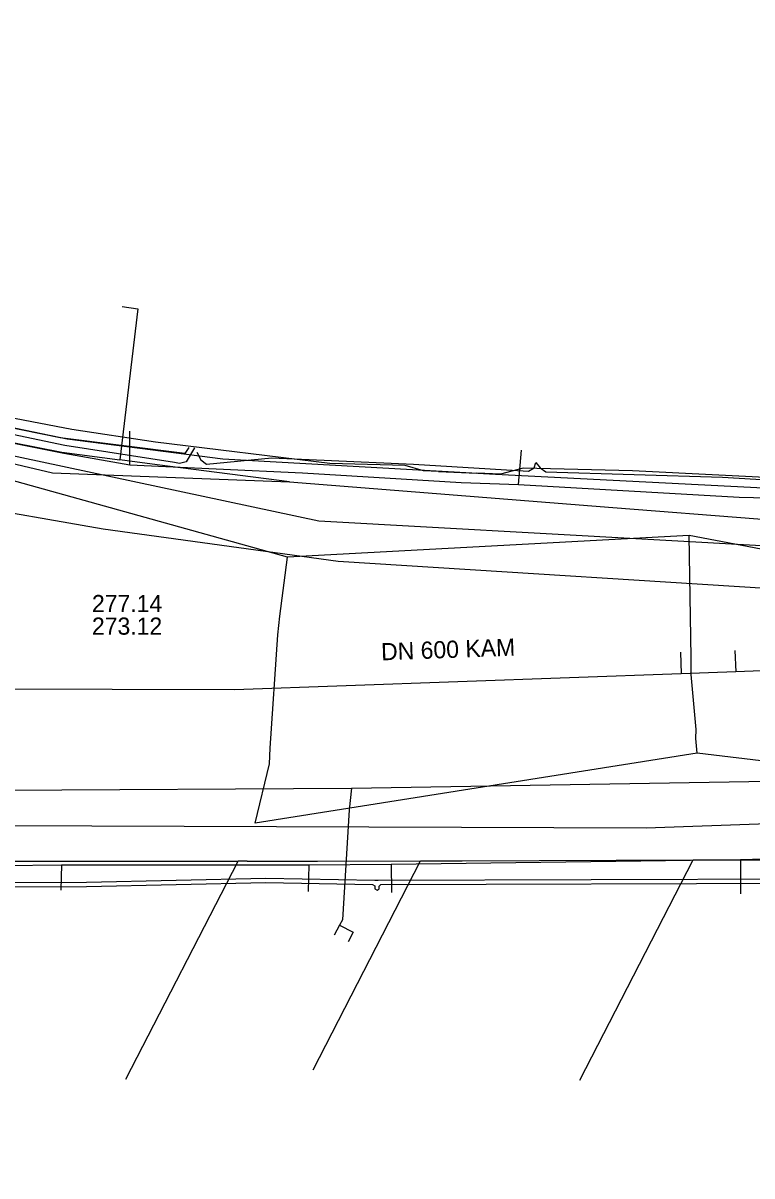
# Model space of a CAD drawing. Extents: x -600309 to -598967, y -1161267 to -1160292.
# Drawn here: x -599941.2 to -599907.3, y -1160644.2 to -1160590.5 of the extents above; entities that cross this region are included whole.
import ezdxf

# ---------------------------------------------------------------- set-up
doc = ezdxf.new("R2010")
doc.units = 0
for name, color, linetype in [('Vrstva 12', 7, 'Continuous'), ('Vrstva 13', 7, 'Continuous'), ('Vrstva 19', 7, 'Continuous'), ('Vrstva 42', 7, 'Continuous'), ('Vrstva 44', 7, 'Continuous'), ('Vrstva 54', 7, 'Continuous'), ('Vrstva 55', 7, 'Continuous'), ('Vrstva 58', 7, 'Continuous'), ('Vrstva 9', 7, 'Continuous')]:
    doc.layers.add(name, color=color, linetype=linetype)

msp = doc.modelspace()

# ---------------------------------------------------------------- linework, layer by layer
at = {"layer": 'Vrstva 12'}
for points in [[(-599936.59, -1160603.7), (-599935.85, -1160603.81), (-599936.69, -1160610.83)], [(-599964.95, -1160612.45), (-599960.36, -1160606.89), (-599959.61, -1160605.99), (-599952.18, -1160608.55), (-599943.72, -1160610.52), (-599939.82, -1160611.43), (-599928.8, -1160611.86), (-599934.95, -1160611.06)], [(-599928.8, -1160611.86), (-599913.75, -1160613.05)], [(-599913.75, -1160613.05), (-599907, -1160613.58), (-599905.71, -1160613.64), (-599901.71, -1160613.81), (-599894.61, -1160614.11)], [(-599951.69, -1160629.51), (-599943.72, -1160629.5), (-599939.43, -1160629.5)], [(-599939.43, -1160629.5), (-599931.19, -1160629.5)], [(-599936.42, -1160639.65), (-599931.19, -1160629.5)]]:
    msp.add_lwpolyline(points, dxfattribs=at)
at = {"layer": 'Vrstva 13'}
for points in [[(-599964.42, -1160603.13), (-599957.44, -1160605.72), (-599948.29, -1160608.73), (-599939.39, -1160610.48), (-599936.69, -1160610.83)], [(-599970.74, -1160603.76), (-599969.63, -1160604.26), (-599946.75, -1160612.38), (-599944.23, -1160612.86), (-599937.46, -1160614.05), (-599926.53, -1160615.54), (-599903.43, -1160617), (-599890.037, -1160617.72), (-599889.007, -1160617.75)], [(-599934.95, -1160611.06), (-599936.69, -1160610.83)], [(-599979.856, -1160625.833), (-599963.124, -1160626.142), (-599942.084, -1160626.199), (-599925.916, -1160626.112), (-599904.64, -1160625.76), (-599890.91, -1160625.33), (-599889.081, -1160625.294)], [(-599925.916, -1160626.112), (-599926.011, -1160627.122), (-599926.334, -1160632.231), (-599926.474, -1160632.487), (-599926.722, -1160632.948)], [(-599930.76, -1160629.5), (-599931.19, -1160629.5)], [(-599930.76, -1160629.5), (-599927.49, -1160629.51), (-599922.7, -1160629.49)], [(-599927.7, -1160639.21), (-599922.7, -1160629.49)], [(-599922.7, -1160629.49), (-599920.76, -1160629.49), (-599910.01, -1160629.45)], [(-599915.28, -1160639.7), (-599910.01, -1160629.45)], [(-599910.01, -1160629.45), (-599906.65, -1160629.44), (-599901.77, -1160629.42), (-599901.3, -1160629.42)], [(-599926.474, -1160632.487), (-599925.837, -1160632.806), (-599926.063, -1160633.267)]]:
    msp.add_lwpolyline(points, dxfattribs=at)
at = {"layer": 'Vrstva 19'}
for points in [[(-599991.95, -1160590.51), (-599991.56, -1160590.68), (-599981.71, -1160595.22), (-599976.24, -1160597.66), (-599967.93, -1160601.45), (-599960.41, -1160604.64), (-599958.16, -1160605.49), (-599953.44, -1160607.21), (-599948.34, -1160608.72), (-599939.3, -1160610.53), (-599936.23, -1160611.06), (-599928.19, -1160611.43), (-599923.6, -1160611.71), (-599920.81, -1160611.88), (-599918.13, -1160611.98), (-599914.08, -1160612.22), (-599907.86, -1160612.57), (-599903.85, -1160612.66)], [(-599936.23, -1160611.06), (-599936.22, -1160609.5)], [(-599918.13, -1160611.98), (-599918, -1160610.38)], [(-599997.23, -1160628.68), (-599986.23, -1160628.15), (-599984.55, -1160628.09), (-599979.81, -1160628.44), (-599977.56, -1160629.6), (-599968.75, -1160629.61), (-599961.95, -1160629.63), (-599951.67, -1160629.66), (-599942.09, -1160629.71), (-599939.41, -1160629.68), (-599927.89, -1160629.67), (-599924.07, -1160629.65), (-599907.8, -1160629.43), (-599903.31, -1160629.31), (-599891.43, -1160629.55), (-599889.35, -1160629.49), (-599887.1, -1160629.56)], [(-599907.8, -1160629.43), (-599907.8, -1160631.03)], [(-599939.41, -1160629.68), (-599939.43, -1160630.845), (-599939.43, -1160630.85)], [(-599927.89, -1160629.67), (-599927.93, -1160630.92)], [(-599924.07, -1160629.65), (-599924.04, -1160630.96)]]:
    msp.add_lwpolyline(points, dxfattribs=at)
at = {"layer": 'Vrstva 42'}
for points in [[(-599933.219, -1160610.274), (-599933.61, -1160610.93), (-599933.91, -1160611.01), (-599934.15, -1160610.96), (-599939.25, -1160610.17), (-599943.17, -1160609.35), (-599946.43, -1160608.69), (-599951.825, -1160607.251), (-599955.09, -1160606.21), (-599958.371, -1160605.104), (-599959.103, -1160604.882), (-599959.601, -1160604.731), (-599959.895, -1160604.642), (-599961.716, -1160603.894), (-599964.478, -1160602.82), (-599970.844, -1160599.898), (-599970.884, -1160599.22), (-599970.196, -1160597.784), (-599969.589, -1160597.966)], [(-599933.475, -1160610.254), (-599933.663, -1160610.542), (-599939.469, -1160609.807), (-599942.996, -1160609.092), (-599946.162, -1160608.438), (-599951.77, -1160607.059), (-599958.33, -1160604.907), (-599959.072, -1160604.839), (-599959.103, -1160604.882), (-599960.296, -1160606.51), (-599965.329, -1160612.567), (-599967.657, -1160614.798), (-599969.445, -1160615.306), (-599974.529, -1160616.071), (-599976.487, -1160616.436), (-599977.443, -1160617.356), (-599978.152, -1160628.4), (-599979.744, -1160631.222), (-599985.025, -1160642.296), (-599988.164, -1160649.123)], [(-599933.11, -1160610.47), (-599932.923, -1160610.828), (-599932.66, -1160611.03), (-599929.61, -1160610.74), (-599923.03, -1160611.03), (-599917.67, -1160611.36), (-599917.41, -1160611.21), (-599917.33, -1160610.95), (-599917.13, -1160611.21), (-599916.87, -1160611.39), (-599908.64, -1160611.64), (-599900.89, -1160612.11)], [(-599986.337, -1160645.444), (-599983.595, -1160639.946), (-599979.531, -1160631.799), (-599979.106, -1160630.858), (-599978.76, -1160630.67), (-599976.055, -1160630.579), (-599968.949, -1160630.339), (-599965.782, -1160630.39), (-599965.461, -1160630.394), (-599959.143, -1160630.417), (-599950.295, -1160630.484), (-599946.898, -1160630.389), (-599946.552, -1160630.43), (-599943.496, -1160630.504), (-599938.249, -1160630.49), (-599929.893, -1160630.304), (-599924.816, -1160630.393), (-599924.665, -1160630.393), (-599904.833, -1160630.334), (-599904.429, -1160630.33), (-599891.023, -1160630.218), (-599889.48, -1160630.29), (-599889.07, -1160630.618), (-599888.966, -1160630.759)], [(-599943.498, -1160630.704), (-599938.247, -1160630.69), (-599929.893, -1160630.504), (-599924.924, -1160630.591), (-599924.819, -1160630.652), (-599924.818, -1160630.791), (-599924.72, -1160630.86), (-599924.619, -1160630.793), (-599924.614, -1160630.663), (-599924.544, -1160630.593), (-599904.956, -1160630.534)]]:
    msp.add_lwpolyline(points, dxfattribs=at)
at = {"layer": 'Vrstva 44'}
for points in [[(-599921.86, -1160611.37), (-599922.55, -1160611.34), (-599923.408, -1160611.092), (-599926.91, -1160611.01), (-599935.03, -1160610.01), (-599938.93, -1160609.42), (-599943.07, -1160608.63), (-599947.62, -1160607.61), (-599951.2, -1160606.69), (-599954.97, -1160605.6), (-599958.78, -1160604.28), (-599959.47, -1160604.27), (-599959.92, -1160604.54), (-599960.2, -1160604.87), (-599961.29, -1160606.42), (-599965.74, -1160612.19), (-599966.89, -1160613.83), (-599968.98, -1160616.23), (-599969.38, -1160616.45), (-599970.12, -1160616.51), (-599971.483, -1160616.193), (-599974.925, -1160616.215)], [(-599921.86, -1160611.37), (-599920.08, -1160611.46)], [(-599905.11, -1160611.74), (-599912.83, -1160611.34), (-599917.916, -1160611.221), (-599918.97, -1160611.5), (-599920.08, -1160611.46)]]:
    msp.add_lwpolyline(points, dxfattribs=at)
at = {"layer": 'Vrstva 54'}
for points in [[(-599910.19, -1160614.353), (-599928.88, -1160615.354), (-599948.114, -1160610.011)], [(-599866.787, -1160616.099), (-599890.26, -1160618.142), (-599910.19, -1160614.353)], [(-599909.814, -1160624.487), (-599909.884, -1160623.794), (-599909.861, -1160623.379), (-599910.099, -1160620.822), (-599910.104, -1160620.023), (-599910.19, -1160614.353)], [(-599930.393, -1160627.733), (-599929.724, -1160624.97), (-599929.687, -1160624.241), (-599929.343, -1160618.972), (-599929.245, -1160618.104), (-599928.88, -1160615.354)], [(-599889.49, -1160626.913), (-599909.814, -1160624.487), (-599930.393, -1160627.733)]]:
    msp.add_lwpolyline(points, dxfattribs=at)
at = {"layer": 'Vrstva 55'}
for points in [[(-599864.16, -1160616.98), (-599896.25, -1160615.43), (-599927.43, -1160613.69), (-599956.474, -1160607.502)], [(-599989.01, -1160630.77), (-599989.001, -1160628.167), (-599950.924, -1160627.821), (-599912.197, -1160627.951), (-599889.974, -1160627.171), (-599847.04, -1160627.06)]]:
    msp.add_lwpolyline(points, dxfattribs=at)
at = {"layer": 'Vrstva 58'}
msp.add_lwpolyline([(-599904.29, -1160612.28), (-599919.21, -1160611.52), (-599931.89, -1160610.8), (-599939.15, -1160609.87), (-599946.7, -1160608.31), (-599954.18, -1160606.27), (-599958.51, -1160604.88), (-599960.47, -1160607.02), (-599965.6, -1160612.44)], dxfattribs=at)
at = {"layer": 'Vrstva 9'}
for p, q in [((-599910.6, -1160619.789), (-599910.564, -1160620.788)), ((-599908.061, -1160619.697), (-599908.025, -1160620.696))]:
    msp.add_line(p, q, dxfattribs=at)
for points in [[(-599885.47, -1160619.88), (-599905.597, -1160620.608), (-599908.025, -1160620.696), (-599910.564, -1160620.788), (-599931.35, -1160621.54)], [(-599931.35, -1160621.54), (-599942.75, -1160621.51), (-599948.47, -1160621.495), (-599949.75, -1160621.492), (-599958.033, -1160621.478)]]:
    msp.add_lwpolyline(points, dxfattribs=at)

# ---------------------------------------------------------------- texts
at = {"layer": 'Vrstva 12'}
for s, p in [('277.14', (-599937.99, -1160617.92)), ('273.12', (-599937.99, -1160618.97))]:
    msp.add_text(s, height=0.8, dxfattribs=at).set_placement(p)
msp.add_text('DN 600 KAM', height=0.8, rotation=2.0626, dxfattribs=at).set_placement((-599924.518, -1160620.166))

doc.saveas('drawing.dxf')
